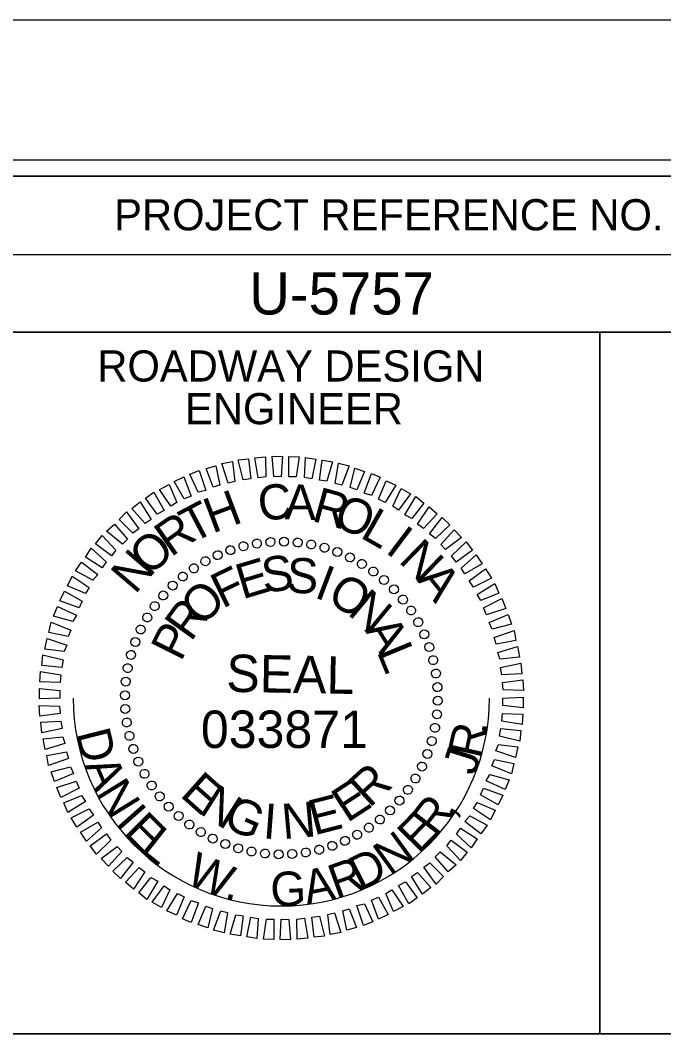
# Model space of a CAD drawing. Extents: x 957297 to 961629, y 830661 to 840840.
# Drawn here: x 960184.9 to 960288, y 834216.4 to 834378.9 of the extents above; entities that cross this region are included whole.
import ezdxf

# ---------------------------------------------------------------- set-up
doc = ezdxf.new("R2010")
doc.units = 0
for name, color, linetype in [('Scratch_Level_0', 7, 'Continuous'), ('Sheet Data Field CELL', 7, 'Continuous'), ('Sheet Plot Border Inside CELL', 7, 'Continuous'), ('Sheet Plot Border Outside CELL', 7, 'Continuous'), ('Sheet Professional Seal CELL', 7, 'Continuous'), ('Sheet Profile Grid Minor CELL', 7, 'Continuous'), ('Sheet Sticker Exception Certification CELL', 7, 'Continuous'), ('Sheet Typical CELL', 7, 'Continuous')]:
    doc.layers.add(name, color=color, linetype=linetype)

msp = doc.modelspace()

# ---------------------------------------------------------------- linework, layer by layer
at = {"layer": 'Scratch_Level_0'}
msp.add_arc((960226.74, 834270.2), 33.36, 180, 360, dxfattribs=at)
at = {"layer": 'Sheet Plot Border Inside CELL'}
msp.add_lwpolyline([(960390.3, 834356.46), (958723.8, 834356.46), (958723.8, 833301.36), (960390.3, 833301.36)], close=True, dxfattribs=at)
at = {"layer": 'Sheet Plot Border Outside CELL'}
msp.add_lwpolyline([(960394.8, 834378.91), (958710.8, 834378.91), (958710.8, 833278.91), (960394.8, 833278.91)], close=True, dxfattribs=at)
at = {"layer": 'Sheet Professional Seal CELL'}
for p, q in [((960218.54, 834293.95), (960218.54, 834293.95)), ((960220.64, 834294.55), (960220.64, 834294.55)), ((960222.84, 834294.95), (960222.84, 834294.95)), ((960224.99, 834295.25), (960224.99, 834295.25)), ((960227.19, 834295.3), (960227.19, 834295.3)), ((960229.39, 834295.15), (960229.39, 834295.15)), ((960231.54, 834294.8), (960231.54, 834294.8)), ((960233.64, 834294.35), (960233.64, 834294.35)), ((960216.54, 834293.15), (960216.54, 834293.15)), ((960235.74, 834293.65), (960235.74, 834293.65)), ((960237.74, 834292.75), (960237.74, 834292.75)), ((960212.69, 834291), (960212.69, 834291)), ((960214.59, 834292.15), (960214.59, 834292.15)), ((960239.69, 834291.75), (960239.69, 834291.75)), ((960210.94, 834289.75), (960210.94, 834289.75)), ((960241.49, 834290.5), (960241.49, 834290.5)), ((960243.24, 834289.15), (960243.24, 834289.15)), ((960209.29, 834288.25), (960209.29, 834288.25)), ((960244.79, 834287.65), (960244.79, 834287.65)), ((960207.79, 834286.7), (960207.79, 834286.7)), ((960246.29, 834286), (960246.29, 834286)), ((960206.44, 834284.95), (960206.44, 834284.95)), ((960247.54, 834284.25), (960247.54, 834284.25)), ((960205.19, 834283.15), (960205.19, 834283.15)), ((960204.19, 834281.2), (960204.19, 834281.2)), ((960248.69, 834282.35), (960248.69, 834282.35)), ((960249.69, 834280.4), (960249.69, 834280.4)), ((960203.29, 834279.2), (960203.29, 834279.2)), ((960250.49, 834278.4), (960250.49, 834278.4)), ((960202.59, 834277.1), (960202.59, 834277.1)), ((960251.09, 834276.3), (960251.09, 834276.3)), ((960202.14, 834275), (960202.14, 834275)), ((960201.79, 834272.85), (960201.79, 834272.85)), ((960251.49, 834274.1), (960251.49, 834274.1)), ((960251.79, 834271.95), (960251.79, 834271.95)), ((960201.64, 834270.65), (960201.64, 834270.65)), ((960226.74, 834270.2), (960226.74, 834270.2)), ((960251.84, 834269.75), (960251.84, 834269.75)), ((960201.69, 834268.45), (960201.69, 834268.45)), ((960251.69, 834267.55), (960251.69, 834267.55)), ((960201.99, 834266.3), (960201.99, 834266.3)), ((960251.34, 834265.4), (960251.34, 834265.4)), ((960202.39, 834264.1), (960202.39, 834264.1)), ((960250.89, 834263.3), (960250.89, 834263.3)), ((960202.99, 834262), (960202.99, 834262)), ((960203.79, 834260), (960203.79, 834260)), ((960250.19, 834261.2), (960250.19, 834261.2)), ((960249.29, 834259.2), (960249.29, 834259.2)), ((960204.79, 834258.05), (960204.79, 834258.05)), ((960248.29, 834257.25), (960248.29, 834257.25)), ((960205.94, 834256.15), (960205.94, 834256.15)), ((960247.04, 834255.45), (960247.04, 834255.45)), ((960207.19, 834254.4), (960207.19, 834254.4)), ((960245.69, 834253.7), (960245.69, 834253.7)), ((960208.69, 834252.75), (960208.69, 834252.75)), ((960244.19, 834252.15), (960244.19, 834252.15)), ((960210.24, 834251.25), (960210.24, 834251.25)), ((960242.54, 834250.65), (960242.54, 834250.65)), ((960211.99, 834249.9), (960211.99, 834249.9)), ((960213.79, 834248.65), (960213.79, 834248.65)), ((960240.79, 834249.4), (960240.79, 834249.4)), ((960215.74, 834247.65), (960215.74, 834247.65)), ((960236.94, 834247.25), (960236.94, 834247.25)), ((960238.89, 834248.25), (960238.89, 834248.25)), ((960217.74, 834246.75), (960217.74, 834246.75)), ((960219.84, 834246.05), (960219.84, 834246.05)), ((960221.94, 834245.6), (960221.94, 834245.6)), ((960224.09, 834245.25), (960224.09, 834245.25)), ((960230.64, 834245.45), (960230.64, 834245.45)), ((960232.84, 834245.85), (960232.84, 834245.85)), ((960234.94, 834246.45), (960234.94, 834246.45)), ((960226.29, 834245.1), (960226.29, 834245.1)), ((960228.49, 834245.15), (960228.49, 834245.15))]:
    msp.add_line(p, q, dxfattribs=at)
for points in [[(960223.04, 834305.5), (960222.49, 834308.7), (960224.19, 834308.9), (960224.24, 834305.65)], [(960225.54, 834305.75), (960225.29, 834309), (960226.94, 834308.95), (960226.74, 834305.7)], [(960227.94, 834305.7), (960227.94, 834308.95), (960229.59, 834308.9), (960229.14, 834305.65)], [(960230.44, 834305.55), (960230.64, 834308.8), (960232.29, 834308.5), (960231.64, 834305.35)], [(960215.84, 834304), (960214.69, 834307), (960216.24, 834307.45), (960216.89, 834304.35)], [(960218.24, 834304.65), (960217.19, 834307.8), (960218.89, 834308.15), (960219.29, 834304.9)], [(960220.64, 834305.2), (960219.84, 834308.4), (960221.49, 834308.55), (960221.84, 834305.35)], [(960232.84, 834305.15), (960233.29, 834308.35), (960234.94, 834308.1), (960234.04, 834305)], [(960235.39, 834304.6), (960235.89, 834307.85), (960237.59, 834307.45), (960236.44, 834304.35)], [(960237.79, 834303.95), (960238.54, 834307.05), (960240.09, 834306.55), (960238.84, 834303.6)], [(960211.19, 834302.15), (960209.59, 834304.95), (960211.14, 834305.65), (960212.29, 834302.6)], [(960213.39, 834303.2), (960212.09, 834306.1), (960213.59, 834306.7), (960214.64, 834303.5)], [(960240.04, 834303.05), (960241.19, 834306.2), (960242.59, 834305.6), (960241.19, 834302.7)], [(960209.04, 834300.95), (960207.19, 834303.65), (960208.74, 834304.45), (960209.99, 834301.55)], [(960242.29, 834302.1), (960243.54, 834305.05), (960245.09, 834304.35), (960243.39, 834301.55)], [(960244.59, 834300.95), (960245.94, 834303.8), (960247.44, 834302.95), (960245.54, 834300.35)], [(960206.84, 834299.7), (960204.99, 834302.25), (960206.29, 834303.2), (960207.94, 834300.3)], [(960246.54, 834299.6), (960248.29, 834302.5), (960249.59, 834301.45), (960247.64, 834299)], [(960204.94, 834298.2), (960202.79, 834300.6), (960204.14, 834301.65), (960205.89, 834298.85)], [(960248.59, 834298.1), (960250.44, 834300.85), (960251.74, 834299.75), (960249.54, 834297.4)], [(960202.94, 834296.65), (960200.74, 834298.85), (960201.94, 834300.05), (960203.89, 834297.35)], [(960250.49, 834296.55), (960252.54, 834299.15), (960253.74, 834297.95), (960251.44, 834295.8)], [(960201.29, 834294.9), (960198.74, 834296.95), (960199.99, 834298.1), (960202.09, 834295.7)], [(960199.54, 834293), (960196.94, 834294.95), (960198.04, 834296.25), (960200.24, 834293.9)], [(960252.29, 834294.8), (960254.44, 834297.15), (960255.64, 834295.95), (960253.04, 834294)], [(960198.04, 834291.1), (960195.34, 834292.8), (960196.29, 834294.25), (960198.69, 834292.05)], [(960254.04, 834293), (960256.34, 834295.25), (960257.39, 834293.9), (960254.74, 834292)], [(960255.54, 834291.05), (960257.99, 834293.15), (960258.94, 834291.7), (960256.14, 834290.1)], [(960196.54, 834289.1), (960193.74, 834290.6), (960194.74, 834292), (960197.34, 834290)], [(960256.84, 834289), (960259.49, 834290.9), (960260.44, 834289.4), (960257.54, 834288)], [(960195.34, 834286.95), (960192.49, 834288.2), (960193.24, 834289.75), (960195.94, 834287.9)], [(960258.14, 834286.8), (960260.94, 834288.55), (960261.59, 834287), (960258.74, 834285.85)], [(960194.34, 834284.65), (960191.24, 834285.8), (960191.99, 834287.35), (960194.84, 834285.75)], [(960259.14, 834284.65), (960262.09, 834286.15), (960262.74, 834284.55), (960259.64, 834283.55)], [(960193.34, 834282.45), (960190.24, 834283.35), (960190.89, 834284.9), (960193.89, 834283.5)], [(960260.04, 834282.3), (960263.09, 834283.6), (960263.64, 834282.05), (960260.54, 834281.25)], [(960192.59, 834280.05), (960189.49, 834280.7), (960189.84, 834282.35), (960192.99, 834281.1)], [(960260.84, 834279.9), (960264.04, 834281.05), (960264.34, 834279.4), (960261.19, 834278.85)], [(960191.94, 834277.65), (960188.84, 834278.05), (960189.19, 834279.75), (960192.34, 834278.7)], [(960261.44, 834277.5), (960264.59, 834278.45), (960264.89, 834276.75), (960261.74, 834276.45)], [(960191.54, 834275.1), (960188.34, 834275.4), (960188.54, 834277.1), (960191.79, 834276.3)], [(960191.29, 834272.7), (960188.04, 834272.8), (960188.14, 834274.45), (960191.39, 834273.9)], [(960261.89, 834275.1), (960265.14, 834275.8), (960265.29, 834274.1), (960262.09, 834273.9)], [(960262.19, 834272.7), (960265.44, 834273.1), (960265.54, 834271.4), (960262.29, 834271.5)], [(960191.24, 834270.2), (960187.99, 834270.05), (960187.99, 834271.75), (960191.24, 834271.4)], [(960262.24, 834270.2), (960265.49, 834270.35), (960265.49, 834268.65), (960262.24, 834269)], [(960191.29, 834267.7), (960188.04, 834267.3), (960187.94, 834269), (960191.19, 834268.9)], [(960191.59, 834265.3), (960188.34, 834264.6), (960188.19, 834266.3), (960191.39, 834266.5)], [(960262.19, 834267.7), (960265.44, 834267.6), (960265.34, 834265.95), (960262.09, 834266.5)], [(960261.94, 834265.3), (960265.14, 834265), (960264.94, 834263.3), (960261.69, 834264.1)], [(960192.04, 834262.9), (960188.89, 834261.95), (960188.59, 834263.65), (960191.74, 834263.95)], [(960192.64, 834260.5), (960189.44, 834259.35), (960189.14, 834261), (960192.29, 834261.55)], [(960261.54, 834262.75), (960264.64, 834262.35), (960264.29, 834260.65), (960261.14, 834261.7)], [(960260.89, 834260.35), (960263.99, 834259.7), (960263.64, 834258.05), (960260.49, 834259.3)], [(960193.44, 834258.1), (960190.39, 834256.8), (960189.84, 834258.35), (960192.94, 834259.15)], [(960194.34, 834255.75), (960191.39, 834254.25), (960190.74, 834255.85), (960193.84, 834256.85)], [(960260.14, 834257.95), (960263.24, 834257.05), (960262.59, 834255.5), (960259.59, 834256.9)], [(960259.14, 834255.75), (960262.24, 834254.6), (960261.49, 834253.05), (960258.64, 834254.65)], [(960195.34, 834253.6), (960192.54, 834251.85), (960191.89, 834253.4), (960194.74, 834254.55)], [(960258.14, 834253.45), (960260.99, 834252.2), (960260.24, 834250.65), (960257.54, 834252.5)], [(960196.64, 834251.4), (960193.99, 834249.5), (960193.04, 834251), (960195.94, 834252.4)], [(960197.94, 834249.35), (960195.49, 834247.25), (960194.54, 834248.7), (960197.34, 834250.3)], [(960256.94, 834251.3), (960259.74, 834249.8), (960258.74, 834248.4), (960256.14, 834250.4)], [(960255.44, 834249.3), (960258.14, 834247.6), (960257.19, 834246.15), (960254.79, 834248.35)], [(960199.44, 834247.4), (960197.14, 834245.15), (960196.09, 834246.5), (960198.74, 834248.4)], [(960253.94, 834247.4), (960256.54, 834245.45), (960255.44, 834244.15), (960253.24, 834246.5)], [(960201.19, 834245.6), (960199.04, 834243.25), (960197.84, 834244.45), (960200.44, 834246.4)], [(960252.19, 834245.5), (960254.74, 834243.45), (960253.49, 834242.3), (960251.39, 834244.7)], [(960202.99, 834243.85), (960200.94, 834241.25), (960199.74, 834242.45), (960202.04, 834244.6)], [(960250.54, 834243.75), (960252.74, 834241.55), (960251.54, 834240.35), (960249.59, 834243.05)], [(960204.89, 834242.3), (960203.04, 834239.55), (960201.74, 834240.65), (960203.94, 834243)], [(960248.54, 834242.2), (960250.69, 834239.8), (960249.34, 834238.75), (960247.59, 834241.55)], [(960206.94, 834240.8), (960205.19, 834237.9), (960203.89, 834238.95), (960205.84, 834241.4)], [(960246.64, 834240.7), (960248.49, 834238.15), (960247.19, 834237.2), (960245.54, 834240.1)], [(960208.89, 834239.45), (960207.54, 834236.6), (960206.04, 834237.45), (960207.94, 834240.05)], [(960211.19, 834238.3), (960209.94, 834235.35), (960208.39, 834236.05), (960210.09, 834238.85)], [(960244.44, 834239.45), (960246.29, 834236.75), (960244.74, 834235.95), (960243.49, 834238.85)], [(960213.44, 834237.35), (960212.29, 834234.2), (960210.89, 834234.8), (960212.29, 834237.7)], [(960240.09, 834237.2), (960241.39, 834234.3), (960239.89, 834233.7), (960238.84, 834236.9)], [(960242.29, 834238.25), (960243.89, 834235.45), (960242.34, 834234.75), (960241.19, 834237.8)], [(960215.69, 834236.45), (960214.94, 834233.35), (960213.39, 834233.85), (960214.64, 834236.8)], [(960218.09, 834235.8), (960217.59, 834232.55), (960215.89, 834232.95), (960217.04, 834236.05)], [(960235.24, 834235.75), (960236.29, 834232.6), (960234.59, 834232.25), (960234.19, 834235.5)], [(960237.64, 834236.4), (960238.79, 834233.4), (960237.24, 834232.95), (960236.59, 834236.05)], [(960220.64, 834235.25), (960220.19, 834232.05), (960218.54, 834232.3), (960219.44, 834235.4)], [(960223.04, 834234.85), (960222.84, 834231.6), (960221.19, 834231.9), (960221.84, 834235.05)], [(960225.54, 834234.7), (960225.54, 834231.45), (960223.89, 834231.5), (960224.34, 834234.75)], [(960227.94, 834234.65), (960228.19, 834231.4), (960226.54, 834231.45), (960226.74, 834234.7)], [(960230.44, 834234.9), (960230.99, 834231.7), (960229.29, 834231.5), (960229.24, 834234.75)], [(960232.84, 834235.2), (960233.64, 834232), (960231.99, 834231.85), (960231.64, 834235.05)]]:
    msp.add_lwpolyline(points, close=True, dxfattribs=at)
for centre, major_axis in [((960222.82, 834294.97), (-0.113, 0.711)), ((960224.99, 834295.22), (-0.05, 0.718)), ((960227.18, 834295.28), (0.013, 0.72)), ((960229.37, 834295.14), (0.075, 0.716)), ((960231.53, 834294.82), (0.137, 0.707)), ((960218.58, 834293.91), (-0.234, 0.681)), ((960220.68, 834294.54), (-0.174, 0.699)), ((960233.66, 834294.31), (0.198, 0.692)), ((960235.73, 834293.61), (0.258, 0.672)), ((960214.58, 834292.14), (-0.349, 0.63)), ((960216.54, 834293.11), (-0.293, 0.658)), ((960237.74, 834292.74), (0.316, 0.647)), ((960239.66, 834291.7), (0.371, 0.617)), ((960212.72, 834290.99), (-0.403, 0.597)), ((960241.49, 834290.49), (0.423, 0.582)), ((960210.96, 834289.69), (-0.453, 0.56)), ((960243.2, 834289.13), (0.472, 0.543)), ((960207.82, 834286.65), (-0.543, 0.472)), ((960209.32, 834288.24), (-0.5, 0.518)), ((960244.79, 834287.62), (0.518, 0.5)), ((960246.23, 834285.98), (0.56, 0.453)), ((960206.45, 834284.94), (-0.582, 0.423)), ((960247.54, 834284.23), (0.597, 0.403)), ((960205.25, 834283.12), (-0.617, 0.371)), ((960248.68, 834282.36), (0.63, 0.349)), ((960204.2, 834281.19), (-0.647, 0.316)), ((960249.66, 834280.4), (0.658, 0.293)), ((960203.33, 834279.19), (-0.672, 0.258)), ((960202.64, 834277.11), (-0.692, 0.198)), ((960250.46, 834278.37), (0.681, 0.234)), ((960251.08, 834276.27), (0.699, 0.174)), ((960202.12, 834274.99), (-0.707, 0.137)), ((960251.52, 834274.12), (0.711, 0.113)), ((960201.8, 834272.82), (-0.716, 0.075)), ((960201.67, 834270.64), (-0.72, 0.013)), ((960251.76, 834271.95), (0.718, 0.05)), ((960251.82, 834269.76), (0.72, -0.013)), ((960201.73, 834268.45), (-0.718, -0.05)), ((960251.69, 834267.58), (0.716, -0.075)), ((960201.97, 834266.28), (-0.711, -0.113)), ((960202.41, 834264.13), (-0.699, -0.174)), ((960251.36, 834265.42), (0.707, -0.137)), ((960250.85, 834263.29), (0.692, -0.198)), ((960203.03, 834262.04), (-0.681, -0.234)), ((960250.16, 834261.21), (0.672, -0.258)), ((960203.83, 834260), (-0.658, -0.293)), ((960249.29, 834259.21), (0.647, -0.316)), ((960204.81, 834258.04), (-0.63, -0.349)), ((960205.95, 834256.18), (-0.597, -0.403)), ((960248.24, 834257.28), (0.617, -0.371)), ((960207.25, 834254.42), (-0.56, -0.453)), ((960247.03, 834255.46), (0.582, -0.423)), ((960208.7, 834252.78), (-0.518, -0.5)), ((960245.67, 834253.75), (0.543, -0.472)), ((960210.29, 834251.27), (-0.472, -0.543)), ((960244.17, 834252.16), (0.5, -0.518)), ((960212, 834249.91), (-0.423, -0.582)), ((960240.77, 834249.41), (0.403, -0.597)), ((960242.53, 834250.71), (0.453, -0.56)), ((960213.83, 834248.7), (-0.371, -0.617)), ((960215.75, 834247.66), (-0.316, -0.647)), ((960238.9, 834248.27), (0.349, -0.63)), ((960217.76, 834246.79), (-0.258, -0.672)), ((960219.83, 834246.09), (-0.198, -0.692)), ((960234.91, 834246.49), (0.234, -0.681)), ((960236.94, 834247.29), (0.293, -0.658)), ((960221.96, 834245.58), (-0.137, -0.707)), ((960224.12, 834245.26), (-0.075, -0.716)), ((960226.31, 834245.12), (-0.013, -0.72)), ((960228.49, 834245.18), (0.05, -0.718)), ((960230.67, 834245.43), (0.113, -0.711)), ((960232.81, 834245.87), (0.174, -0.699))]:
    msp.add_ellipse(centre, major_axis=major_axis, ratio=0.999708, dxfattribs=at)
at = {"layer": 'Sheet Sticker Exception Certification CELL'}
msp.add_line((960177.75, 834216.36), (960377.79, 834216.36), dxfattribs=at)
at = {"layer": 'Sheet Typical CELL'}
for p, q in [((960177.75, 834341.36), (960377.8, 834341.36)), ((960277.8, 834328.86), (960277.8, 834216.41))]:
    msp.add_line(p, q, dxfattribs=at)
for points in [[(960377.8, 834353.91), (958877.8, 834353.91), (958877.8, 833303.91), (960377.8, 833303.91)], [(960177.75, 834353.91), (960377.8, 834353.91), (960377.8, 834328.86), (960177.75, 834328.86)], [(960177.75, 834328.86), (960277.8, 834328.86), (960277.8, 834216.36), (960177.75, 834216.36)], [(960277.8, 834328.86), (960377.8, 834328.86), (960377.8, 834216.36), (960277.8, 834216.36)]]:
    msp.add_lwpolyline(points, close=True, dxfattribs=at)

# ---------------------------------------------------------------- texts
at = {"layer": 'Sheet Data Field CELL'}
msp.add_text('U-5757', height=6.75, dxfattribs=at).set_placement((960221.59, 834331.71))
at = {"layer": 'Sheet Professional Seal CELL'}
for s, height, rotation, p in [('C', 5.64, 6.2199, (960223.29, 834298.55)), ('A', 5.64, 359.0203, (960227.24, 834298.85)), ('R', 5.64, 344.6211, (960231.44, 834298.65)), ('H', 5.64, 20.6195, (960215.69, 834296.55)), ('O', 5.64, 337.4212, (960234.79, 834297.9)), ('T', 5.64, 27.8198, (960212.44, 834294.9)), ('L', 5.64, 330.2209, (960239.19, 834296.05)), ('R', 5.64, 35.0205, (960209.04, 834292.7)), ('I', 5.64, 323.0201, (960243.24, 834293.65)), ('O', 5.64, 42.2217, (960205.59, 834289.6)), ('N', 5.64, 315.8189, (960245.39, 834292.1)), ('N', 5.64, 49.4235, (960203.29, 834286.7)), ('E', 5.64, 16.6111, (960220.49, 834286)), ('S', 5.64, 7.2556, (960223.94, 834287.05)), ('S', 5.64, 357.9004, (960227.54, 834287.1)), ('F', 5.64, 25.967, (960217.29, 834284.5)), ('I', 5.64, 339.1896, (960231.84, 834286.4)), ('A', 5.64, 308.6172, (960248.34, 834289.15)), ('O', 5.64, 329.8335, (960233.84, 834285.7)), ('O', 5.64, 44.6812, (960213.99, 834281.55)), ('N', 5.64, 320.4766, (960237.19, 834283.7)), ('R', 5.64, 54.0396, (960212.24, 834279.1)), ('P', 5.64, 63.3989, (960210.64, 834275.9)), ('A', 5.64, 301.7603, (960240.04, 834281.1)), ('L', 5.64, 292.4008, (960241.99, 834277.65)), ('SEAL', 5.998, 359, (960217.89, 834271.2)), ('E', 5.64, 318.2769, (960210.34, 834254.55)), ('R', 5.64, 42.4814, (960240.84, 834252.45)), ('E', 5.64, 33.1241, (960237.29, 834250.1)), ('N', 5.64, 327.634, (960213.34, 834251.85)), ('G', 5.64, 336.9902, (960217.14, 834249.6)), ('N', 5.64, 5.0564, (960227.04, 834247.55)), ('E', 5.64, 14.4118, (960231.99, 834248.15)), ('I', 5.64, 355.7012, (960223.69, 834247.7))]:
    msp.add_text(s, height=height, rotation=rotation, dxfattribs=at).set_placement(p)
at = {"layer": 'Sheet Profile Grid Minor CELL'}
for s, height, rotation, p in [('033871', 5.998, 360, (960213.85, 834262.19)), ('D', 5.5, 284.2682, (960193.75, 834264.56)), ('R', 5.5, 77.3541, (960258.72, 834260.3)), ('.', 5.5, 84.2805, (960259.68, 834264.23)), ('J', 5.5, 72.4855, (960257.76, 834257.62)), ('A', 5.5, 293.4128, (960195.07, 834259.39)), ('N', 5.5, 301.5986, (960196.93, 834254.99)), ('R', 5.5, 52.3788, (960251.55, 834247.73)), ('I', 5.5, 311.5304, (960200, 834250.07)), ('E', 5.5, 315.0508, (960201.29, 834248.47)), ('E', 5.5, 45.7958, (960248.8, 834245.03)), (',', 5.5, 59.3052, (960254.07, 834250.88)), ('L', 5.5, 321.6338, (960203.95, 834245.69)), ('N', 5.5, 35.8641, (960244.13, 834241.6)), ('W', 5.5, 336.8891, (960211.2, 834240.56)), ('D', 5.5, 26.7195, (960239.37, 834239.2)), ('R', 5.5, 19.793, (960235.54, 834237.91)), ('G', 5.5, 1.6755, (960225.06, 834236.77)), ('A', 5.5, 11.6072, (960230.85, 834236.98)), ('.', 5.5, 348.4952, (960217.48, 834238.04))]:
    msp.add_text(s, height=height, rotation=rotation, dxfattribs=at).set_placement(p)
at = {"layer": 'Sheet Typical CELL'}
for s, height, p in [('PROJECT REFERENCE NO.', 5.0001, (960199.95, 834345.21)), ('ROADWAY DESIGN', 5.0001, (960197.25, 834320.96)), ('ENGINEER', 5, (960211.3, 834314.11))]:
    msp.add_text(s, height=height, dxfattribs=at).set_placement(p)

doc.saveas('drawing.dxf')
